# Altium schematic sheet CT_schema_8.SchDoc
size 278 x 170 mm
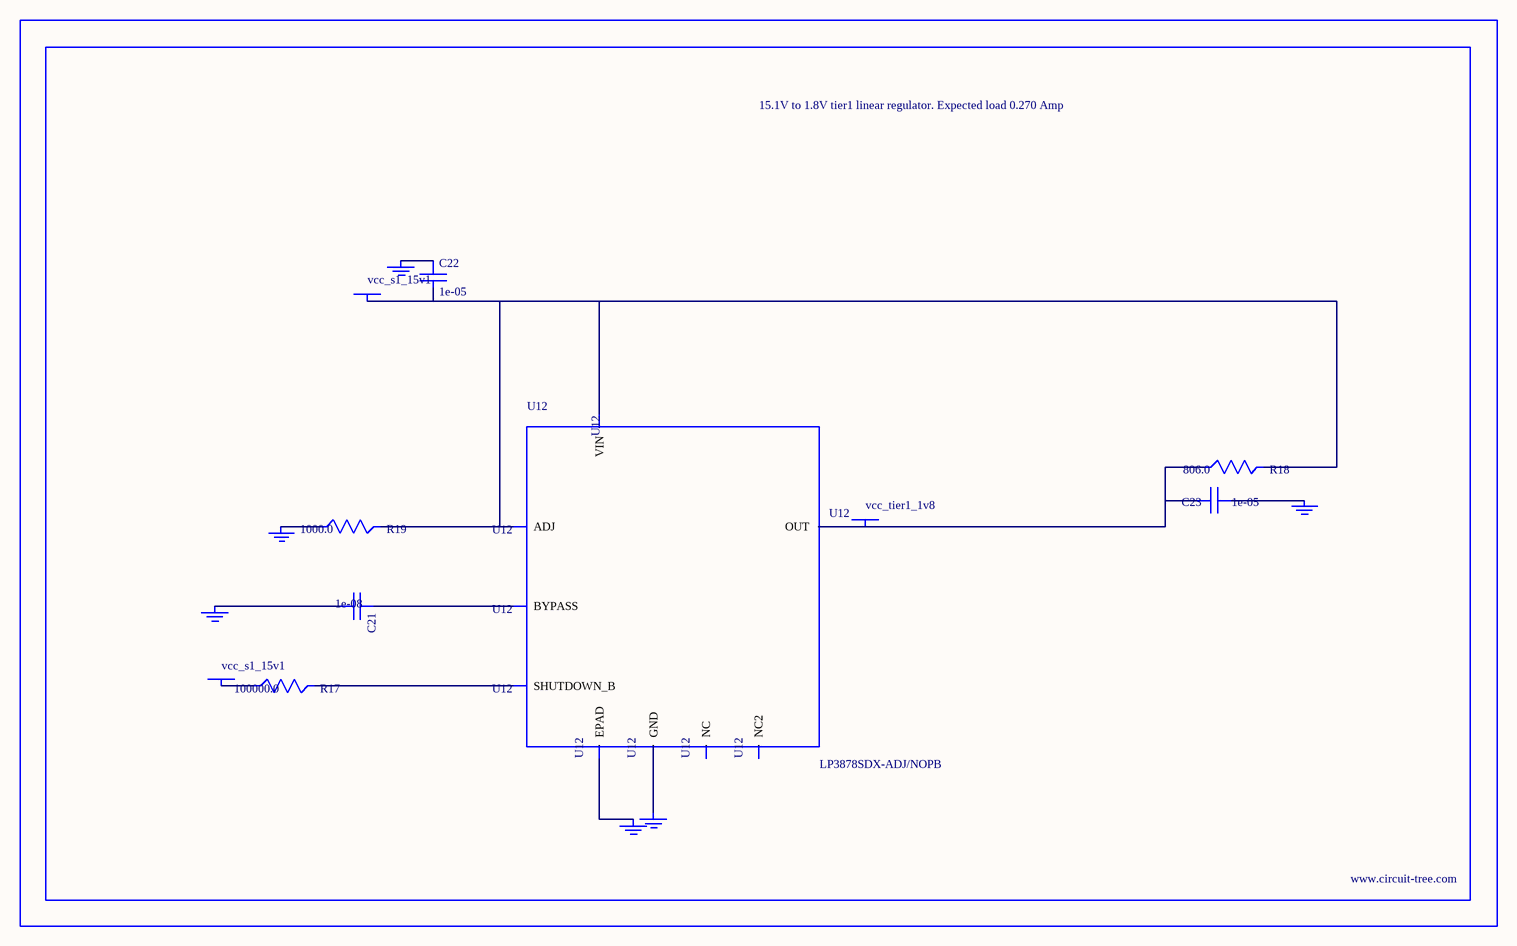
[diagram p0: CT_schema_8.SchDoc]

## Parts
BORDER7  (no value)
C21  1e-08  [C0402]
C22  1e-05  [C1210]
C23  1e-05  [C0805]
GND_INSTANCE_7_0  (no value)
GND_INSTANCE_7_1  (no value)
GND_INSTANCE_7_2  (no value)
GND_INSTANCE_7_3  (no value)
GND_INSTANCE_7_4  (no value)
GND_INSTANCE_7_5  (no value)
POWER_INSTANCE_7_0  vcc_s1_15v1
POWER_INSTANCE_7_1  vcc_s1_15v1
POWER_INSTANCE_7_2  vcc_tier1_1v8
R17  100000.0  [R0603]
R18  806.0  [R0603]
R19  1000.0  [R0603]
U12  LP3878SDX-ADJ/NOPB  [WSON-8]

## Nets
NetC21_1: C21.1 U12.1(BYPASS)
NetC21_2: C21.2 GND_INSTANCE_7_0.0(GND)
NetC22_1: C22.1 GND_INSTANCE_7_1.0(GND)
NetC22_2: C22.2 POWER_INSTANCE_7_0.0(PWR) R18.2 R19.2 U12.4(VIN) U12.6(ADJ)
NetC23_1: C23.1 GND_INSTANCE_7_2.0(GND)
NetC23_2: C23.2 POWER_INSTANCE_7_2.0(PWR) R18.1 U12.5(OUT)
NetGND_INSTANCE_7_3_0: GND_INSTANCE_7_3.0(GND) R19.1
NetGND_INSTANCE_7_4_0: GND_INSTANCE_7_4.0(GND) U12.PAD(EPAD)
NetGND_INSTANCE_7_5_0: GND_INSTANCE_7_5.0(GND) U12.3(GND)
NetPOWER_INSTANCE_7_1_0: POWER_INSTANCE_7_1.0(PWR) R17.1
NetR17_2: R17.2 U12.8(SHUTDOWN_B)

Not connected (* = marked no-connect by the designer): U12 2(NC) 7(NC2)

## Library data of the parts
BORDER7 = BORDER_PAGE7
C21 = C0402C103K3RAC
C22 = C1210C106K5PACTU
C23 = GRM219R60J106ME19D
GND_INSTANCE_7_0-GND_INSTANCE_7_5 = GND
POWER_INSTANCE_7_0-POWER_INSTANCE_7_2 = PWR
R17 = RC0603JR-07100KL
R18 = ERJ-3EKF8060V
R19 = RC0603JR-071KL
